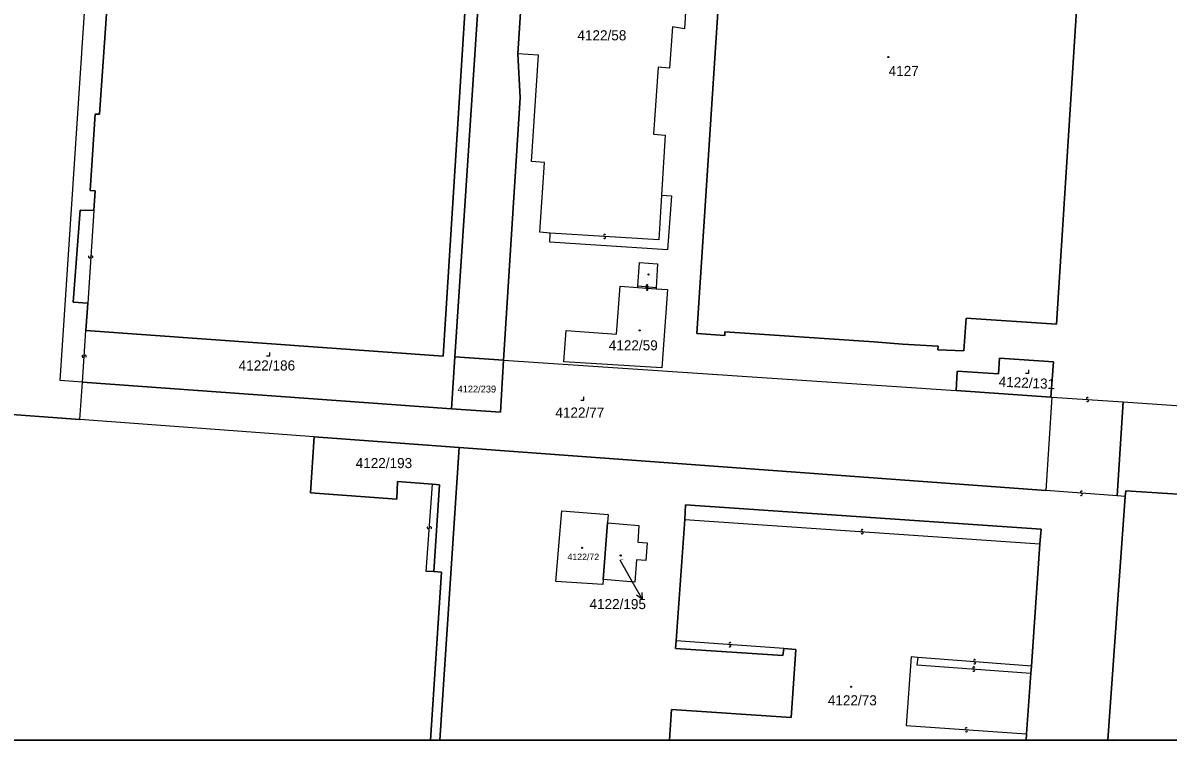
# Model space of a CAD drawing. Extents: x -598233 to -596890, y -1157848 to -1156431.
# Drawn here: x -598049.8 to -597857.6, y -1157848.5 to -1157728 of the extents above; entities that cross this region are included whole.
import ezdxf

# ---------------------------------------------------------------- set-up
doc = ezdxf.new("R2010")
doc.units = 0
for name, color, linetype in [('Level 1', 7, 'Continuous'), ('Level 13', 7, 'Continuous'), ('Level 3', 7, 'Continuous'), ('Level 4', 7, 'Continuous'), ('Level 5', 7, 'Continuous'), ('Level 57', 7, 'Continuous'), ('Level 60', 7, 'Continuous'), ('Vrstva 60', 7, 'Continuous'), ('zajmove_uzemi', 7, 'Continuous')]:
    doc.layers.add(name, color=color, linetype=linetype)

msp = doc.modelspace()

# ---------------------------------------------------------------- linework, layer by layer
at = {"layer": 'Level 1'}
for p, q in [((-597979.84, -1157848.46), (-597976.61, -1157799.31)), ((-597881.33, -1157847.42), (-597881.4, -1157848.46)), ((-597866.71, -1157848.42), (-597865.99, -1157848.46))]:
    msp.add_line(p, q, dxfattribs=at)
for points in [[(-598034.89, -1157656.85), (-598032.81, -1157625.6), (-597967.14, -1157630.18), (-597977.32, -1157784.11)], [(-598039.27, -1157779.68), (-597979.3, -1157783.98), (-597972.63, -1157678.32), (-597971.83, -1157678.39), (-597968.5, -1157630.72), (-598029.32, -1157626.61), (-598032.66, -1157673.56), (-598032.09, -1157673.58), (-598036.96, -1157743.37), (-598037.69, -1157743.34), (-598038.54, -1157756.19), (-598037.74, -1157756.24), (-598037.94, -1157759.53)], [(-598039.85, -1157788.33), (-598043.6, -1157788.06), (-598034.89, -1157656.85)], [(-597927.38, -1157688.73), (-597930.68, -1157688.52), (-597936.67, -1157780.19), (-597932.01, -1157780.5), (-597931.98, -1157779.93), (-597906.97, -1157781.59), (-597902.14, -1157781.97), (-597896.18, -1157782.3), (-597896.23, -1157782.9), (-597891.85, -1157783.08), (-597891.49, -1157777.6), (-597876.31, -1157778.64), (-597870.79, -1157692.41), (-597884.62, -1157691.51)], [(-597966.74, -1157733.21), (-597964.2, -1157694.04)], [(-597937.77, -1157712.34), (-597938.78, -1157729.01), (-597940.8, -1157728.7), (-597941.25, -1157735.61), (-597943.17, -1157735.47), (-597943.98, -1157746.71), (-597941.98, -1157746.86), (-597942.6, -1157756.97)], [(-597969.13, -1157784.66), (-597966.34, -1157740.61), (-597966.74, -1157733.21)], [(-597961.29, -1157763.32), (-597963.06, -1157763.17), (-597962.25, -1157751.47), (-597964.45, -1157751.32), (-597963.28, -1157733.46), (-597966.74, -1157733.21)], [(-597942.6, -1157756.97), (-597940.95, -1157757.04), (-597941.6, -1157766.11), (-597961.37, -1157764.84), (-597961.29, -1157763.32)], [(-598037.94, -1157759.53), (-598040.22, -1157759.46), (-598041.41, -1157774.91), (-598038.97, -1157775.1)], [(-597946.57, -1157772.24), (-597946.32, -1157768.25), (-597943.28, -1157768.47), (-597943.49, -1157772.49)], [(-597943.5, -1157772.67), (-597941.61, -1157772.8), (-597942.59, -1157785.92), (-597959.02, -1157784.95), (-597958.6, -1157779.67), (-597950.18, -1157780.32), (-597949.54, -1157772.25), (-597946.58, -1157772.45)], [(-597946.58, -1157772.45), (-597946.57, -1157772.24)], [(-597943.49, -1157772.49), (-597943.5, -1157772.67)], [(-598038.97, -1157775.1), (-598039.27, -1157779.68)], [(-597977.9, -1157792.81), (-597977.32, -1157784.11)], [(-597977.9, -1157792.81), (-597969.68, -1157793.4), (-597969.13, -1157784.66)], [(-597977.32, -1157784.11), (-597969.13, -1157784.66)], [(-597969.13, -1157784.66), (-597893.17, -1157789.78)], [(-597877.27, -1157790.85), (-597876.8, -1157784.95), (-597885.85, -1157784.34), (-597886.05, -1157786.94), (-597892.96, -1157786.52), (-597893.17, -1157789.78)], [(-598040.28, -1157794.62), (-598039.85, -1157788.33)], [(-598039.85, -1157788.33), (-597977.9, -1157792.81)], [(-597893.17, -1157789.78), (-597877.27, -1157790.85)], [(-597877.09, -1157790.86), (-597878.1, -1157806.57)], [(-597877.27, -1157790.85), (-597877.09, -1157790.86)], [(-598070.67, -1157792.38), (-598040.28, -1157794.62)], [(-597865.12, -1157791.67), (-597866.13, -1157807.45)], [(-597865.12, -1157791.67), (-597849.69, -1157792.71)], [(-598000.93, -1157797.52), (-598040.28, -1157794.62)], [(-597981.09, -1157805.47), (-597986.95, -1157805.05), (-597987.06, -1157807.98), (-598001.56, -1157806.94), (-598000.93, -1157797.52)], [(-598000.93, -1157797.52), (-597976.61, -1157799.31)], [(-597976.61, -1157799.31), (-597878.1, -1157806.57)], [(-597981.09, -1157805.47), (-597979.9, -1157805.58), (-597980.87, -1157820.14)], [(-597864.74, -1157807.55), (-597864.67, -1157806.61), (-597766.7, -1157812.9), (-597766.83, -1157814.77)], [(-597867.7, -1157848.46), (-597867.53, -1157846.09), (-597864.74, -1157807.55)], [(-597864.74, -1157807.55), (-597866.13, -1157807.45)], [(-597952.42, -1157821.5), (-597952.49, -1157822.35), (-597960.35, -1157821.83), (-597959.37, -1157809.96), (-597951.57, -1157810.6), (-597951.68, -1157812)], [(-597938.73, -1157811.41), (-597938.61, -1157808.94), (-597878.85, -1157813.03), (-597879.09, -1157815.49)], [(-597951.68, -1157812), (-597952.42, -1157821.5)], [(-597951.68, -1157812), (-597946.4, -1157812.41), (-597946.61, -1157815.2), (-597945.02, -1157815.33), (-597945.25, -1157818.32), (-597946.83, -1157818.21), (-597947.09, -1157821.92), (-597952.42, -1157821.5)], [(-597940.14, -1157831.78), (-597938.73, -1157811.41)], [(-597879.09, -1157815.49), (-597880.52, -1157836.03)], [(-597981.42, -1157848.46), (-597979.55, -1157820.28), (-597980.87, -1157820.14)], [(-597922.1, -1157833.1), (-597922.23, -1157834.27), (-597940.26, -1157833.07), (-597940.14, -1157831.78)], [(-597941.25, -1157848.46), (-597940.92, -1157843.35), (-597920.84, -1157844.65), (-597920.08, -1157833.25), (-597922.1, -1157833.1)], [(-597880.62, -1157837.23), (-597881.33, -1157847.42)], [(-597880.52, -1157836.03), (-597880.62, -1157837.23)]]:
    msp.add_lwpolyline(points, dxfattribs=at)
at = {"layer": 'Level 13'}
for centre, start, end in [((-597952.16, -1157763.71), 33.5819, 266.1719), ((-597952.18, -1157764.07), 213.7964, 85.8944), ((-598038.64, -1157767.31), 123.3735, 355.9635), ((-598038.28, -1157767.33), 303.588, 175.686), ((-597945.03, -1157772.38), 33.2871, 265.3851), ((-597945.01, -1157772.18), 32.5178, 265.1078), ((-597945.05, -1157772.74), 213.0727, 85.6627), ((-597945.05, -1157772.54), 212.7323, 84.8303), ((-598039.74, -1157783.99), 123.5367, 355.6347), ((-598039.38, -1157784.01), 303.3222, 175.9122), ((-597871.09, -1157791.09), 33.5015, 265.5995), ((-597871.11, -1157791.45), 213.287, 85.877), ((-597872.11, -1157806.83), 32.9536, 265.5436), ((-597872.14, -1157807.19), 213.1681, 85.2661), ((-597981.78, -1157812.79), 123.3538, 355.4518), ((-597981.42, -1157812.81), 303.1393, 175.7293), ((-597908.9, -1157813.27), 33.4592, 265.5572), ((-597908.92, -1157813.63), 213.2447, 85.8347), ((-597931.11, -1157832.26), 32.9734, 265.5634), ((-597931.14, -1157832.62), 213.1878, 85.2858), ((-597890.04, -1157835.12), 32.778, 265.368), ((-597890.07, -1157835.48), 212.9924, 85.0904), ((-597890.18, -1157836.35), 33.1914, 265.2894), ((-597890.21, -1157836.71), 212.977, 85.567), ((-597891.43, -1157846.55), 33.4402, 265.5382), ((-597891.45, -1157846.91), 213.2257, 85.8157)]:
    msp.add_arc(centre, 0.184, start, end, dxfattribs=at)
at = {"layer": 'Level 3'}
for points in [[(-597942.6, -1157756.97), (-597943.05, -1157764.46), (-597961.29, -1157763.32)], [(-598037.94, -1157759.53), (-598038.97, -1157775.1)], [(-597943.49, -1157772.49), (-597946.57, -1157772.24)], [(-597946.58, -1157772.45), (-597943.5, -1157772.67)], [(-598039.85, -1157788.33), (-598039.27, -1157779.68)], [(-597877.09, -1157790.86), (-597865.12, -1157791.67)], [(-597980.87, -1157820.14), (-597982.12, -1157820.13), (-597981.09, -1157805.47)], [(-597866.13, -1157807.45), (-597878.1, -1157806.57)], [(-597938.73, -1157811.41), (-597879.09, -1157815.49)], [(-597922.1, -1157833.1), (-597940.14, -1157831.78)], [(-597899.58, -1157834.57), (-597900.72, -1157834.49), (-597901.55, -1157846.03), (-597881.33, -1157847.42)], [(-597899.58, -1157834.57), (-597899.77, -1157835.83), (-597880.62, -1157837.23)], [(-597880.52, -1157836.03), (-597899.58, -1157834.57)]]:
    msp.add_lwpolyline(points, dxfattribs=at)
at = {"layer": 'Level 5'}
for points in [[(-598008.95, -1157783.94), (-598008.4, -1157783.94), (-598008.4, -1157783.39)], [(-597881.5, -1157786.82), (-597880.95, -1157786.82), (-597880.95, -1157786.27)], [(-597956.19, -1157791.38), (-597955.64, -1157791.38), (-597955.64, -1157790.83)]]:
    msp.add_lwpolyline(points, dxfattribs=at)
for centre, radius in [((-597904.53, -1157733.77), 0.09), ((-597904.53, -1157733.77), 0.0521), ((-597944.8, -1157770.28), 0.09), ((-597944.8, -1157770.28), 0.0521), ((-597946.29, -1157779.67), 0.09), ((-597946.29, -1157779.67), 0.0521), ((-597955.94, -1157816.18), 0.09), ((-597955.94, -1157816.18), 0.0521), ((-597949.47, -1157817.46), 0.09), ((-597949.47, -1157817.46), 0.0521), ((-597910.78, -1157839.51), 0.09), ((-597910.78, -1157839.51), 0.0521)]:
    msp.add_circle(centre, radius, dxfattribs=at)
at = {"layer": 'Level 57'}
for p, q in [((-597949.61, -1157818.2), (-597947.37, -1157822.16)), ((-597947.37, -1157822.16), (-597945.89, -1157824.77))]:
    msp.add_line(p, q, dxfattribs=at)
msp.add_lwpolyline([(-597945.95, -1157823.65), (-597945.89, -1157824.77), (-597946.82, -1157824.15)], dxfattribs=at)
at = {"layer": 'Level 60'}
for points in [[(-597909.06, -1157627.95), (-597906.18, -1157583.28), (-597901.61, -1157583.57), (-597903.17, -1157607.81), (-597904.85, -1157633.91), (-597940.04, -1157631.73), (-597958.41, -1157630.64), (-597959.51, -1157642.87), (-597961.55, -1157671.94), (-597963.85, -1157688.75), (-597964.2, -1157694.04), (-597966.74, -1157733.21), (-597966.34, -1157740.61), (-597969.13, -1157784.66), (-597977.32, -1157784.11), (-597967.14, -1157630.18), (-598032.81, -1157625.6), (-598034.89, -1157656.85), (-598047.12, -1157656.06), (-598044.6, -1157619.18)], [(-598039.85, -1157788.33), (-598043.6, -1157788.06), (-598034.89, -1157656.85), (-598032.81, -1157625.6), (-597967.14, -1157630.18), (-597977.32, -1157784.11), (-597977.9, -1157792.81)], [(-597979.3, -1157783.98), (-597972.63, -1157678.32), (-597971.83, -1157678.39), (-597968.5, -1157630.72), (-598029.32, -1157626.61), (-598032.66, -1157673.56), (-598032.09, -1157673.58), (-598036.96, -1157743.37), (-598037.69, -1157743.34), (-598038.54, -1157756.19), (-598037.74, -1157756.24), (-598037.94, -1157759.53), (-598040.22, -1157759.46), (-598041.41, -1157774.91), (-598038.97, -1157775.1), (-598039.27, -1157779.68)], [(-597972.63, -1157678.32), (-597979.3, -1157783.98), (-598039.27, -1157779.68), (-598038.97, -1157775.1), (-598041.41, -1157774.91), (-598040.22, -1157759.46), (-598037.94, -1157759.53), (-598037.74, -1157756.24), (-598038.54, -1157756.19), (-598037.69, -1157743.34), (-598036.96, -1157743.37), (-598032.09, -1157673.58), (-598032.66, -1157673.56), (-598029.32, -1157626.61), (-597968.5, -1157630.72), (-597971.83, -1157678.39)], [(-597930.68, -1157688.52), (-597927.38, -1157688.73), (-597927.32, -1157687.3), (-597925.2, -1157687.47), (-597925.28, -1157688.84), (-597895.52, -1157690.8), (-597895.08, -1157684.12), (-597892.42, -1157682.39), (-597886.39, -1157683.01), (-597886.81, -1157689.5), (-597884.5, -1157689.65), (-597884.62, -1157691.51), (-597870.79, -1157692.41), (-597876.31, -1157778.64), (-597891.49, -1157777.6), (-597891.85, -1157783.08), (-597896.23, -1157782.9), (-597896.18, -1157782.3), (-597902.14, -1157781.97), (-597906.97, -1157781.59), (-597931.98, -1157779.93), (-597932.01, -1157780.5), (-597936.67, -1157780.19)], [(-597946.57, -1157772.24), (-597946.32, -1157768.25), (-597943.28, -1157768.47), (-597943.49, -1157772.49), (-597943.5, -1157772.67), (-597941.61, -1157772.8), (-597942.59, -1157785.92), (-597959.02, -1157784.95), (-597958.6, -1157779.67), (-597950.18, -1157780.32), (-597949.54, -1157772.25), (-597946.58, -1157772.45)], [(-598000.93, -1157797.52), (-598040.28, -1157794.62), (-598039.85, -1157788.33), (-597977.9, -1157792.81), (-597969.68, -1157793.4), (-597969.13, -1157784.66), (-597893.17, -1157789.78), (-597877.27, -1157790.85), (-597877.09, -1157790.86), (-597878.1, -1157806.57), (-597976.61, -1157799.31)], [(-597969.68, -1157793.4), (-597977.9, -1157792.81), (-597977.32, -1157784.11), (-597969.13, -1157784.66)], [(-597877.27, -1157790.85), (-597893.17, -1157789.78), (-597892.96, -1157786.52), (-597886.05, -1157786.94), (-597885.85, -1157784.34), (-597876.8, -1157784.95)], [(-597841.22, -1157793.33), (-597745.18, -1157799.46), (-597746.27, -1157816.29), (-597766.83, -1157814.77), (-597766.7, -1157812.9), (-597864.67, -1157806.61), (-597864.74, -1157807.55), (-597866.13, -1157807.45), (-597865.12, -1157791.67), (-597849.69, -1157792.71)], [(-597952.49, -1157822.35), (-597960.35, -1157821.83), (-597959.37, -1157809.96), (-597951.57, -1157810.6), (-597951.68, -1157812), (-597952.42, -1157821.5)], [(-597952.42, -1157821.5), (-597951.68, -1157812), (-597946.4, -1157812.41), (-597946.61, -1157815.2), (-597945.02, -1157815.33), (-597945.25, -1157818.32), (-597946.83, -1157818.21), (-597947.09, -1157821.92)]]:
    msp.add_lwpolyline(points, close=True, dxfattribs=at)
msp.add_lwpolyline([(-597937.77, -1157712.34), (-597938.78, -1157729.01), (-597940.8, -1157728.7), (-597941.25, -1157735.61), (-597943.17, -1157735.47), (-597943.98, -1157746.71), (-597941.98, -1157746.86), (-597942.6, -1157756.97), (-597940.95, -1157757.04), (-597941.6, -1157766.11), (-597961.37, -1157764.84), (-597961.29, -1157763.32), (-597963.06, -1157763.17), (-597962.25, -1157751.47), (-597964.45, -1157751.32), (-597963.28, -1157733.46), (-597966.74, -1157733.21), (-597964.2, -1157694.04)], dxfattribs=at)
at = {"layer": 'Vrstva 60'}
for points in [[(-598232.89, -1156430.86), (-598232.89, -1157835.58), (-598232.81, -1157835.6), (-598231.24, -1157835.95), (-598223.73, -1157837.73), (-598218.75, -1157838.85), (-598190.54, -1157845.18), (-598175.89, -1157848.46), (-598170.51, -1157848.46), (-598170.38, -1157848.22), (-598166.89, -1157841.65), (-598165.3, -1157838.66), (-598164.37, -1157836.9), (-598161.86, -1157832.18), (-598161.19, -1157830.95), (-598160.05, -1157828.86), (-598157.63, -1157824.55), (-598144.71, -1157839.14), (-598136.41, -1157848.46), (-597003.66, -1157848.46)], [(-598070.67, -1157792.38), (-598040.28, -1157794.62), (-598039.85, -1157788.33), (-598043.6, -1157788.06), (-598034.89, -1157656.85), (-598047.12, -1157656.06), (-598044.6, -1157619.18), (-597909.06, -1157627.95), (-597906.18, -1157583.28)], [(-597937.77, -1157712.34), (-597938.78, -1157729.01), (-597940.8, -1157728.7), (-597941.25, -1157735.61), (-597943.17, -1157735.47), (-597943.98, -1157746.71), (-597941.98, -1157746.86), (-597942.6, -1157756.97), (-597940.95, -1157757.04), (-597941.6, -1157766.11), (-597961.37, -1157764.84), (-597961.29, -1157763.32), (-597963.06, -1157763.17), (-597962.25, -1157751.47), (-597964.45, -1157751.32), (-597963.28, -1157733.46), (-597966.74, -1157733.21), (-597966.34, -1157740.61), (-597969.13, -1157784.66), (-597893.17, -1157789.78), (-597892.96, -1157786.52), (-597886.05, -1157786.94), (-597885.85, -1157784.34), (-597876.8, -1157784.95), (-597877.27, -1157790.85), (-597877.09, -1157790.86), (-597878.1, -1157806.57), (-597976.61, -1157799.31), (-597979.84, -1157848.46), (-597941.25, -1157848.46), (-597940.92, -1157843.35), (-597920.84, -1157844.65), (-597920.08, -1157833.25), (-597922.1, -1157833.1), (-597922.23, -1157834.27), (-597940.26, -1157833.07), (-597940.14, -1157831.78), (-597938.73, -1157811.41), (-597938.61, -1157808.94), (-597878.85, -1157813.03), (-597879.09, -1157815.49), (-597880.52, -1157836.03), (-597880.62, -1157837.23), (-597881.33, -1157847.42), (-597881.4, -1157848.46), (-597867.7, -1157848.46), (-597867.53, -1157846.09), (-597864.74, -1157807.55), (-597866.13, -1157807.45), (-597865.12, -1157791.67), (-597849.69, -1157792.71)], [(-598111.96, -1157848.46), (-597981.42, -1157848.46), (-597979.55, -1157820.28), (-597980.87, -1157820.14), (-597979.9, -1157805.58), (-597981.09, -1157805.47), (-597986.95, -1157805.05), (-597987.06, -1157807.98), (-598001.56, -1157806.94), (-598000.93, -1157797.52), (-598040.28, -1157794.62), (-598070.67, -1157792.38)]]:
    msp.add_lwpolyline(points, dxfattribs=at)
for points in [[(-597927.32, -1157687.3), (-597925.2, -1157687.47), (-597925.28, -1157688.84), (-597895.52, -1157690.8), (-597895.08, -1157684.12), (-597892.42, -1157682.39), (-597886.39, -1157683.01), (-597886.81, -1157689.5), (-597884.5, -1157689.65), (-597884.62, -1157691.51), (-597870.79, -1157692.41), (-597876.31, -1157778.64), (-597891.49, -1157777.6), (-597891.85, -1157783.08), (-597896.23, -1157782.9), (-597896.18, -1157782.3), (-597902.14, -1157781.97), (-597906.97, -1157781.59), (-597931.98, -1157779.93), (-597932.01, -1157780.5), (-597936.67, -1157780.19), (-597930.68, -1157688.52), (-597927.38, -1157688.73)], [(-597943.28, -1157768.47), (-597943.49, -1157772.49), (-597943.5, -1157772.67), (-597941.61, -1157772.8), (-597942.59, -1157785.92), (-597959.02, -1157784.95), (-597958.6, -1157779.67), (-597950.18, -1157780.32), (-597949.54, -1157772.25), (-597946.58, -1157772.45), (-597946.57, -1157772.24), (-597946.32, -1157768.25)], [(-597981.42, -1157848.46), (-597979.84, -1157848.46), (-597976.61, -1157799.31), (-598000.93, -1157797.52), (-598001.56, -1157806.94), (-597987.06, -1157807.98), (-597986.95, -1157805.05), (-597981.09, -1157805.47), (-597979.9, -1157805.58), (-597980.87, -1157820.14), (-597979.55, -1157820.28)], [(-597867.7, -1157848.46), (-597866.71, -1157848.46), (-597866.71, -1157848.42), (-597865.99, -1157848.46), (-597830.48, -1157848.46), (-597830.48, -1157848.45), (-597830.31, -1157848.46), (-597769.35, -1157848.46), (-597767.74, -1157823.94), (-597770.09, -1157823.78), (-597769.93, -1157821.39), (-597767.28, -1157821.57), (-597766.83, -1157814.77), (-597766.7, -1157812.9), (-597864.67, -1157806.61), (-597864.74, -1157807.55), (-597867.53, -1157846.09)], [(-597959.37, -1157809.96), (-597951.57, -1157810.6), (-597951.68, -1157812), (-597946.4, -1157812.41), (-597946.61, -1157815.2), (-597945.02, -1157815.33), (-597945.25, -1157818.32), (-597946.83, -1157818.21), (-597947.09, -1157821.92), (-597952.42, -1157821.5), (-597952.49, -1157822.35), (-597960.35, -1157821.83)], [(-597941.25, -1157848.46), (-597881.4, -1157848.46), (-597881.33, -1157847.42), (-597880.62, -1157837.23), (-597880.52, -1157836.03), (-597879.09, -1157815.49), (-597878.85, -1157813.03), (-597938.61, -1157808.94), (-597938.73, -1157811.41), (-597940.14, -1157831.78), (-597940.26, -1157833.07), (-597922.23, -1157834.27), (-597922.1, -1157833.1), (-597920.08, -1157833.25), (-597920.84, -1157844.65), (-597940.92, -1157843.35)], [(-597866.71, -1157848.46), (-597865.99, -1157848.46), (-597866.71, -1157848.42)]]:
    msp.add_lwpolyline(points, close=True, dxfattribs=at)
at = {"layer": 'zajmove_uzemi'}
msp.add_lwpolyline([(-598232.89, -1156430.86), (-596890.46, -1156430.86), (-596890.46, -1157848.46), (-598232.89, -1157848.46)], close=True, dxfattribs=at)

# ---------------------------------------------------------------- texts
at = {"layer": 'Level 4'}
for s, height, p in [('4122/58', 1.7, (-597956.74, -1157730.96)), ('4127', 1.7, (-597904.48, -1157736.95)), ('4122/59', 1.7, (-597951.47, -1157783.02)), ('4122/186', 1.7, (-598013.62, -1157786.4)), ('4122/239', 1.16, (-597976.86, -1157790.09)), ('4122/77', 1.7, (-597960.44, -1157794.31)), ('4122/193', 1.7, (-597993.97, -1157802.79)), ('4122/72', 1.1, (-597958.41, -1157818.24)), ('4122/195', 0.1, (-597949.61, -1157818.2)), ('4122/73', 1.7, (-597914.69, -1157842.63))]:
    msp.add_text(s, height=height, dxfattribs=at).set_placement(p)
msp.add_text('4122/131', height=1.7, rotation=357.4144, dxfattribs=at).set_placement((-597886.04, -1157789.1))
at = {"layer": 'Level 57'}
msp.add_text('4122/195', height=1.7, dxfattribs=at).set_placement((-597954.71, -1157826.47))

doc.saveas('drawing.dxf')
